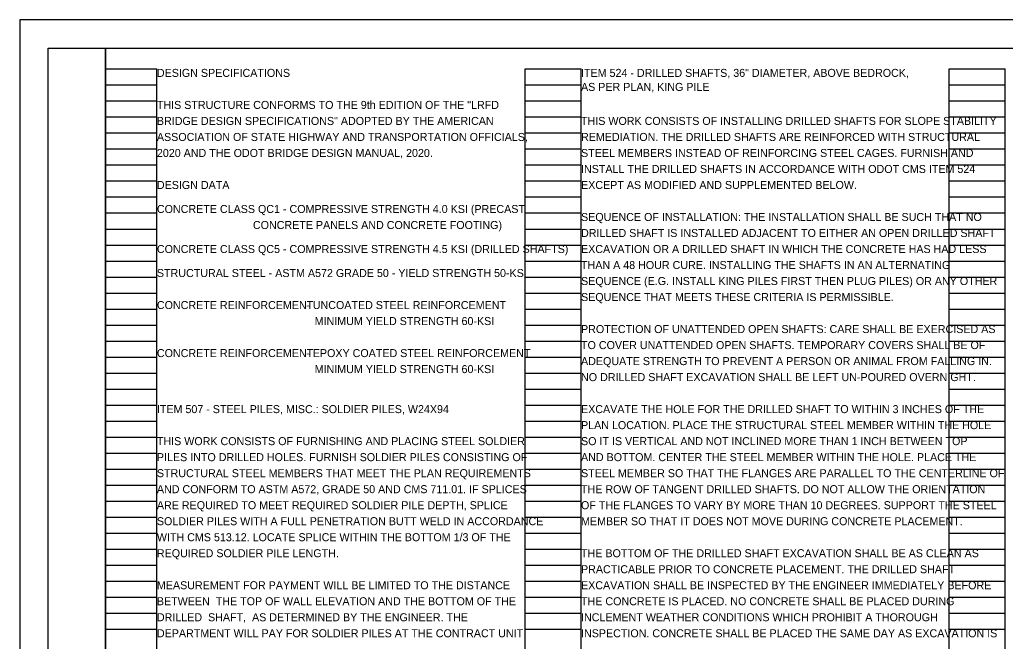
# Model space of a CAD drawing. Extents: x 0 to 51.2, y 0 to 22.
# Drawn here: x 0 to 17.24, y 11.13 to 22 of the extents above; entities that cross this region are included whole.
import ezdxf

# ---------------------------------------------------------------- set-up
doc = ezdxf.new("R2010")
doc.units = 0
for name, color, linetype in [('SH_Border', 7, 'Continuous'), ('SH_Cut_Line', 7, 'Continuous'), ('SH_Data', 7, 'Continuous'), ('SH_Text', 7, 'Continuous'), ('TX_P_1', 7, 'Continuous')]:
    doc.layers.add(name, color=color, linetype=linetype)

msp = doc.modelspace()

# ---------------------------------------------------------------- linework, layer by layer
at = {"layer": 'SH_Border'}
for points in [[(0.5, 21.5), (1.5, 21.5), (1.5, 0.5), (0.5, 0.5)], [(1.5, 21.5), (33.5, 21.5), (33.5, 0.5), (1.5, 0.5)]]:
    msp.add_lwpolyline(points, close=True, dxfattribs=at)
at = {"layer": 'SH_Cut_Line'}
msp.add_lwpolyline([(0, 0), (34, 0), (34, 22), (0, 22)], close=True, dxfattribs=at)
at = {"layer": 'SH_Data'}
for p, q in [((1.5, 0.98), (1.5, 21.14)), ((1.5, 21.14), (2.4, 21.14)), ((2.4, 0.98), (2.4, 21.14)), ((8.84, 0.98), (8.84, 21.14)), ((8.84, 21.14), (9.82, 21.14)), ((9.82, 0.98), (9.82, 21.14)), ((16.26, 0.98), (16.26, 21.14)), ((16.26, 21.14), (17.24, 21.14)), ((17.24, 0.98), (17.24, 21.14)), ((1.5, 20.86), (2.4, 20.86)), ((8.84, 20.86), (9.82, 20.86)), ((16.26, 20.86), (17.24, 20.86)), ((1.5, 20.58), (2.4, 20.58)), ((8.84, 20.58), (9.82, 20.58)), ((16.26, 20.58), (17.24, 20.58)), ((1.5, 20.3), (2.4, 20.3)), ((8.84, 20.3), (9.82, 20.3)), ((16.26, 20.3), (17.24, 20.3)), ((1.5, 20.02), (2.4, 20.02)), ((8.84, 20.02), (9.82, 20.02)), ((16.26, 20.02), (17.24, 20.02)), ((1.5, 19.74), (2.4, 19.74)), ((8.84, 19.74), (9.82, 19.74)), ((16.26, 19.74), (17.24, 19.74)), ((1.5, 19.46), (2.4, 19.46)), ((8.84, 19.46), (9.82, 19.46)), ((16.26, 19.46), (17.24, 19.46)), ((1.5, 19.18), (2.4, 19.18)), ((8.84, 19.18), (9.82, 19.18)), ((16.26, 19.18), (17.24, 19.18)), ((1.5, 18.9), (2.4, 18.9)), ((8.84, 18.9), (9.82, 18.9)), ((16.26, 18.9), (17.24, 18.9)), ((1.5, 18.62), (2.4, 18.62)), ((8.84, 18.62), (9.82, 18.62)), ((16.26, 18.62), (17.24, 18.62)), ((1.5, 18.34), (2.4, 18.34)), ((8.84, 18.34), (9.82, 18.34)), ((16.26, 18.34), (17.24, 18.34)), ((1.5, 18.06), (2.4, 18.06)), ((8.84, 18.06), (9.82, 18.06)), ((16.26, 18.06), (17.24, 18.06)), ((1.5, 17.78), (2.4, 17.78)), ((8.84, 17.78), (9.82, 17.78)), ((16.26, 17.78), (17.24, 17.78)), ((1.5, 17.5), (2.4, 17.5)), ((8.84, 17.5), (9.82, 17.5)), ((16.26, 17.5), (17.24, 17.5)), ((1.5, 17.22), (2.4, 17.22)), ((8.84, 17.22), (9.82, 17.22)), ((16.26, 17.22), (17.24, 17.22)), ((1.5, 16.94), (2.4, 16.94)), ((8.84, 16.94), (9.82, 16.94)), ((16.26, 16.94), (17.24, 16.94)), ((1.5, 16.66), (2.4, 16.66)), ((8.84, 16.66), (9.82, 16.66)), ((16.26, 16.66), (17.24, 16.66)), ((1.5, 16.38), (2.4, 16.38)), ((8.84, 16.38), (9.82, 16.38)), ((16.26, 16.38), (17.24, 16.38)), ((1.5, 16.1), (2.4, 16.1)), ((8.84, 16.1), (9.82, 16.1)), ((16.26, 16.1), (17.24, 16.1)), ((1.5, 15.82), (2.4, 15.82)), ((8.84, 15.82), (9.82, 15.82)), ((16.26, 15.82), (17.24, 15.82)), ((1.5, 15.54), (2.4, 15.54)), ((8.84, 15.54), (9.82, 15.54)), ((16.26, 15.54), (17.24, 15.54)), ((1.5, 15.26), (2.4, 15.26)), ((8.84, 15.26), (9.82, 15.26)), ((16.26, 15.26), (17.24, 15.26)), ((1.5, 14.98), (2.4, 14.98)), ((8.84, 14.98), (9.82, 14.98)), ((16.26, 14.98), (17.24, 14.98)), ((1.5, 14.7), (2.4, 14.7)), ((8.84, 14.7), (9.82, 14.7)), ((16.26, 14.7), (17.24, 14.7)), ((1.5, 14.42), (2.4, 14.42)), ((8.84, 14.42), (9.82, 14.42)), ((16.26, 14.42), (17.24, 14.42)), ((1.5, 14.14), (2.4, 14.14)), ((8.84, 14.14), (9.82, 14.14)), ((16.26, 14.14), (17.24, 14.14)), ((1.5, 13.86), (2.4, 13.86)), ((8.84, 13.86), (9.82, 13.86)), ((16.26, 13.86), (17.24, 13.86)), ((1.5, 13.58), (2.4, 13.58)), ((8.84, 13.58), (9.82, 13.58)), ((16.26, 13.58), (17.24, 13.58)), ((1.5, 13.3), (2.4, 13.3)), ((8.84, 13.3), (9.82, 13.3)), ((16.26, 13.3), (17.24, 13.3)), ((1.5, 13.02), (2.4, 13.02)), ((8.84, 13.02), (9.82, 13.02)), ((16.26, 13.02), (17.24, 13.02)), ((1.5, 12.74), (2.4, 12.74)), ((8.84, 12.74), (9.82, 12.74)), ((16.26, 12.74), (17.24, 12.74)), ((1.5, 12.46), (2.4, 12.46)), ((8.84, 12.46), (9.82, 12.46)), ((16.26, 12.46), (17.24, 12.46)), ((1.5, 12.18), (2.4, 12.18)), ((8.84, 12.18), (9.82, 12.18)), ((16.26, 12.18), (17.24, 12.18)), ((1.5, 11.9), (2.4, 11.9)), ((8.84, 11.9), (9.82, 11.9)), ((16.26, 11.9), (17.24, 11.9)), ((1.5, 11.62), (2.4, 11.62)), ((8.84, 11.62), (9.82, 11.62)), ((16.26, 11.62), (17.24, 11.62)), ((1.5, 11.34), (2.4, 11.34)), ((8.84, 11.34), (9.82, 11.34)), ((16.26, 11.34), (17.24, 11.34))]:
    msp.add_line(p, q, dxfattribs=at)

# ---------------------------------------------------------------- texts
at = {"layer": 'SH_Text'}
for s, p in [('DESIGN SPECIFICATIONS', (2.4, 21)), ('ITEM 524 - DRILLED SHAFTS, 36" DIAMETER, ABOVE BEDROCK, ', (9.82, 21)), ('AS PER PLAN, KING PILE', (9.82, 20.755)), ('THIS STRUCTURE CONFORMS TO THE 9th EDITION OF THE "LRFD ', (2.4, 20.44)), ('BRIDGE DESIGN SPECIFICATIONS" ADOPTED BY THE AMERICAN ', (2.4, 20.16)), ('ASSOCIATION OF STATE HIGHWAY AND TRANSPORTATION OFFICIALS, ', (2.4, 19.88)), ('2020 AND THE ODOT BRIDGE DESIGN MANUAL, 2020.', (2.4, 19.6)), ('DESIGN DATA', (2.4, 19.04)), ('CONCRETE CLASS QC1 - COMPRESSIVE STRENGTH 4.0 KSI (PRECAST ', (2.4, 18.62)), ('CONCRETE PANELS AND CONCRETE FOOTING)', (4.08, 18.34)), ('CONCRETE CLASS QC5 - COMPRESSIVE STRENGTH 4.5 KSI (DRILLED SHAFTS)', (2.4, 17.92)), ('STRUCTURAL STEEL - ASTM A572 GRADE 50 - YIELD STRENGTH 50-KSI', (2.4, 17.5)), ('CONCRETE REINFORCEMENT ', (2.4, 16.94)), ('- UNCOATED STEEL REINFORCEMENT', (5.013, 16.94)), ('          MINIMUM YIELD STRENGTH 60-KSI', (4.64, 16.66)), ('CONCRETE REINFORCEMENT ', (2.4, 16.1)), ('- EPOXY COATED STEEL REINFORCEMENT', (5.013, 16.1)), ('          MINIMUM YIELD STRENGTH 60-KSI', (4.64, 15.82)), ('ITEM 507 - STEEL PILES, MISC.: SOLDIER PILES, W24X94', (2.4, 15.12))]:
    msp.add_text(s, height=0.14, dxfattribs=at).set_placement(p)
at = {"layer": 'TX_P_1'}
for s, p in [('THIS WORK CONSISTS OF INSTALLING DRILLED SHAFTS FOR SLOPE STABILITY ', (9.82, 20.16)), ('REMEDIATION. THE DRILLED SHAFTS ARE REINFORCED WITH STRUCTURAL ', (9.82, 19.88)), ('STEEL MEMBERS INSTEAD OF REINFORCING STEEL CAGES. FURNISH AND ', (9.82, 19.6)), ('INSTALL THE DRILLED SHAFTS IN ACCORDANCE WITH ODOT CMS ITEM 524 ', (9.82, 19.32)), ('EXCEPT AS MODIFIED AND SUPPLEMENTED BELOW.', (9.82, 19.04)), ('SEQUENCE OF INSTALLATION: THE INSTALLATION SHALL BE SUCH THAT NO ', (9.82, 18.48)), ('DRILLED SHAFT IS INSTALLED ADJACENT TO EITHER AN OPEN DRILLED SHAFT ', (9.82, 18.2)), ('EXCAVATION OR A DRILLED SHAFT IN WHICH THE CONCRETE HAS HAD LESS ', (9.82, 17.92)), ('THAN A 48 HOUR CURE. INSTALLING THE SHAFTS IN AN ALTERNATING ', (9.82, 17.64)), ('SEQUENCE (E.G. INSTALL KING PILES FIRST THEN PLUG PILES) OR ANY OTHER ', (9.82, 17.36)), ('SEQUENCE THAT MEETS THESE CRITERIA IS PERMISSIBLE.', (9.82, 17.08)), ('PROTECTION OF UNATTENDED OPEN SHAFTS: CARE SHALL BE EXERCISED AS ', (9.82, 16.52)), ('TO COVER UNATTENDED OPEN SHAFTS. TEMPORARY COVERS SHALL BE OF ', (9.82, 16.24)), ('ADEQUATE STRENGTH TO PREVENT A PERSON OR ANIMAL FROM FALLING IN. ', (9.82, 15.96)), ('NO DRILLED SHAFT EXCAVATION SHALL BE LEFT UN-POURED OVERNIGHT.', (9.82, 15.68)), ('EXCAVATE THE HOLE FOR THE DRILLED SHAFT TO WITHIN 3 INCHES OF THE ', (9.82, 15.12)), ('PLAN LOCATION. PLACE THE STRUCTURAL STEEL MEMBER WITHIN THE HOLE ', (9.82, 14.84)), ('THIS WORK CONSISTS OF FURNISHING AND PLACING STEEL SOLDIER ', (2.4, 14.56)), ('SO IT IS VERTICAL AND NOT INCLINED MORE THAN 1 INCH BETWEEN TOP ', (9.82, 14.56)), ('PILES INTO DRILLED HOLES. FURNISH SOLDIER PILES CONSISTING OF ', (2.4, 14.28)), ('AND BOTTOM. CENTER THE STEEL MEMBER WITHIN THE HOLE. PLACE THE ', (9.82, 14.28)), ('STRUCTURAL STEEL MEMBERS THAT MEET THE PLAN REQUIREMENTS ', (2.4, 14)), ('STEEL MEMBER SO THAT THE FLANGES ARE PARALLEL TO THE CENTERLINE OF ', (9.82, 14)), ('AND CONFORM TO ASTM A572, GRADE 50 AND CMS 711.01. IF SPLICES ', (2.4, 13.72)), ('THE ROW OF TANGENT DRILLED SHAFTS. DO NOT ALLOW THE ORIENTATION ', (9.82, 13.72)), ('ARE REQUIRED TO MEET REQUIRED SOLDIER PILE DEPTH, SPLICE ', (2.4, 13.44)), ('OF THE FLANGES TO VARY BY MORE THAN 10 DEGREES. SUPPORT THE STEEL ', (9.82, 13.44)), ('SOLDIER PILES WITH A FULL PENETRATION BUTT WELD IN ACCORDANCE ', (2.4, 13.16)), ('MEMBER SO THAT IT DOES NOT MOVE DURING CONCRETE PLACEMENT.', (9.82, 13.16)), ('WITH CMS 513.12. LOCATE SPLICE WITHIN THE BOTTOM 1/3 OF THE ', (2.4, 12.88)), ('REQUIRED SOLDIER PILE LENGTH.', (2.4, 12.6)), ('THE BOTTOM OF THE DRILLED SHAFT EXCAVATION SHALL BE AS CLEAN AS ', (9.82, 12.6)), ('PRACTICABLE PRIOR TO CONCRETE PLACEMENT. THE DRILLED SHAFT ', (9.82, 12.32)), ('MEASUREMENT FOR PAYMENT WILL BE LIMITED TO THE DISTANCE ', (2.4, 12.04)), ('EXCAVATION SHALL BE INSPECTED BY THE ENGINEER IMMEDIATELY BEFORE ', (9.82, 12.04)), ('BETWEEN  THE TOP OF WALL ELEVATION AND THE BOTTOM OF THE  ', (2.4, 11.76)), ('THE CONCRETE IS PLACED. NO CONCRETE SHALL BE PLACED DURING ', (9.82, 11.76)), ('DRILLED  SHAFT,  AS DETERMINED BY THE ENGINEER. THE ', (2.4, 11.48)), ('INCLEMENT WEATHER CONDITIONS WHICH PROHIBIT A THOROUGH ', (9.82, 11.48)), ('DEPARTMENT WILL PAY FOR SOLDIER PILES AT THE CONTRACT UNIT  ', (2.4, 11.2)), ('INSPECTION. CONCRETE SHALL BE PLACED THE SAME DAY AS EXCAVATION IS ', (9.82, 11.2))]:
    msp.add_text(s, height=0.14, dxfattribs=at).set_placement(p)

doc.saveas('drawing.dxf')
